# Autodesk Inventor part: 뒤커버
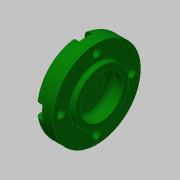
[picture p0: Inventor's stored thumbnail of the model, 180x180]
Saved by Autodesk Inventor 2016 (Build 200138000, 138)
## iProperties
Created: 2015-11
Part Number: 뒤커버
Material: 알루미늄 6061
Document SubType Name: Modeling
Designer: mduedu
Density: 1 g/cm^3
Appearance: 진녹색
Author: mduedu
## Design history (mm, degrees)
sketch "스케치1"
  geometry: L1 (-7, 0)-(7, 0); L2 (-7, 0)-(-7, 26); L3 (-7, 26)-(4, 26); L4 (4, 26)-(4, 16); L5 (4, 16)-(7, 16); L6 (7, 16)-(7, 0); 2 further points
  constraints: 12 end point, 3 perpendicular, 2 parallel, 1 coincident, 1 horizontal, 1 midpoint
  dimensions: "d0" = 14 distance of L1.start L1.end; "d1" = 52 diameter of L3 L1; "d2" = 3 distance of L4.end L5.end; "d3" = 32 diameter of L5 L1
revolve "회전1" sketch "스케치1" stored, may be unused: angle "d4" = 90 deg
hole "구멍1" diameter "d7" = 25; stored, may be unused: countersink angle "d11" = 90 deg, drill point angle "d13" = 0 deg; dims "d8" = 6, "d9" = 4, "d10" = 2, "d12" = 8, "d62" = 10, "d63" = 10
fillet "모깎기2" dims "d36" = 3
fillet "모깎기3" dims "d37" = 3
fillet "모깎기4" dims "d38" = 0.3
sketch "스케치3" dims "d61" = 42
  geometry: C1 r 26 at (0, 0) reference; 2 further points
  constraints: 2 vertical alignment, 1 coincident, 2 other
hole "구멍4" sketch "스케치3" at (0, -21) diameter "d44" = 4.5; stored, may be unused: countersink angle "d48" = 90 deg, drill point angle "d50" = 0 deg; dims "d45" = 6, "d46" = 8, "d47" = 4.6, "d49" = 8
sketch "스케치4"
  geometry: L1 (-4, 0)-(-4, -4.69); L2 (4, 0)-(4, -4.69); A1 r 4 centre (0, 0) between (3.614, -1.714) and (-3.614, -1.714) reference; A2 r 26 centre (0, 21) between (-4, -4.69) and (4, -4.69) reference; 1 further point
  constraints: 4 end point, 4 point on circle, 2 tangent, 1 parallel, 1 vertical
extrude "돌출1" cut sketch "스케치4" stored distance "d51" = 0; taper "d52" = 0 deg
node "솔리드1"
pattern_circular "원형 패턴1" dims angle "d54" = 360 deg
